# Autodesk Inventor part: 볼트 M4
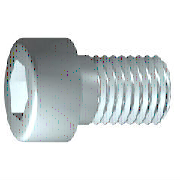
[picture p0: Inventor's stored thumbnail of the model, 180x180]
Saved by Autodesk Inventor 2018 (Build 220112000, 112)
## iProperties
IsCustomPart: 1
Created: 2012-02
Part Number: 볼트 M4
Material: 강철, 연강
Description: 6각머리 태핑 나사
Document SubType Name: Modeling
Standard: KS B 1003
Designer: mduedu
Standards Organization: KS
Language: ko-KR
Size Designation: M 4 x 12
Categories: <MemberInstance><Categories><Category DisplayName="조임쇠" InternalName="e4da775c-781d-43d5-af7c-5136215cf5a6" Mnemonic="FSTN"><Category DisplayName="볼트" InternalN
Density: 1 g/cm^3
Appearance: 강철
Author: mduedu
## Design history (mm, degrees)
sketch "스케치1"
  geometry: L1 (-1, 0)-(12, 0); L2 (12, 0)-(12, 2); L3 (12, 2)-(1.75, 2); L4 (1.75, 2)-(1.32, 2); L5 (1.32, 2)-(0, 2); L6 (0, 2)-(0, 3.5); L7 (0, 3.5)-(-4, 3.5); L8 (-4, 3.5)-(-4, 1.732); L9 (-4, 1.732)-(-2, 1.732); L10 (-2, 1.732)-(-1, 0); L11 (-7.2, 0)-(15.2, 0) reference; L12 (0, -0.7)-(0, 4.2) reference; L13 (1.75, 2)-(0, 2)
  constraints: 22 end point, 6 parallel, 2 collinear, 2 perpendicular, 1 horizontal, 1 point on line
  dimensions: "d1" = 10.25 distance from line of L3.end L2 (= GEL); "d2" = 0.42952 distance of L4.end L3.end (computed from GAL); "d3" = 4 distance between parallel lines of L8 L6 (= KOH); "d4" = 2 distance of L8.end L9.end (= INTI); "d5" = 60 deg angle of L10 L1; "d6" = 4 diameter of L3 L1 (= GD); "d7" = 4 diameter of L5 L1 (= BDM); "d8" = 3.4641 diameter of L9 L1 (= 1.1547 x SW); "d9" = 7 diameter of L7 L1 (= KOD); "d26" = 12 distance between parallel lines of L12 L2 (= NLG)
revolve "본체" sketch "스케치1" stored, may be unused: angle "d10" = 90 deg
sketch "스케치2"
  geometry: L1 (0, -4.9)-(0, 4.9) reference; L2 (-4.9, 0)-(4.9, 0) reference; L3 (1.732, 0)-(0.866, -1.5); L4 (0.866, -1.5)-(-0.866, -1.5); L5 (-0.866, -1.5)-(-1.732, 0); L6 (-1.732, 0)-(-0.866, 1.5); L7 (-0.866, 1.5)-(0.866, 1.5); L8 (0.866, 1.5)-(1.732, 0); 2 further points
  constraints: 12 end point, 1 coincident, 1 horizontal alignment, 1 point on line, 12 other
extrude "슬롯" join sketch "스케치2" stored distance "d11" = 10; taper "d12" = 0 deg
workplane "Work Plane1"
fillet "Fillet2" dims "d30" = 0.1 (= R)
body "Solid1"
fillet "모깎기1" dims "d17" = 0.4 (= RR)
feature "스레드" dims "d13" = 10.25 (= GEL), "d14" = 0
chamfer "모따기1" distance "d15" = 0.42941 (= -0.5 x SPD + 0.5 x GD); stored, may be unused: second distance "d16" = 0.42941 (= GUL), angle "d27" = 45 deg
other parameters: "GD" = 4 (= NND) [user parameter; used in 2 equation terms], "NLG" = 12 [user parameter; used in 1 equation term], "GEL" = 10.25 [user parameter; used in 2 equation terms], "KOD" = 7 [user parameter; used in 1 equation term], "KOH" = 4 [user parameter; used in 1 equation term], "INTI" = 2 [user parameter; used in 1 equation term], "GAL" = 0.42941 (= 0.61345 x PTC) [user parameter; used in 1 equation term], "GUL" = 0.42941 (= 0.61345 x PTC) [user parameter; used in 1 equation term], "BDM" = 4 (= NND) [user parameter; used in 1 equation term], "SW" = 3 [user parameter; used in 2 equation terms], "RR" = 0.4 [user parameter; used in 1 equation term], "SPD" = 3.14117 (= NND - 1.2269 x PTC) [user parameter; used in 1 equation term], "d19" = 0, "d28" = 0, "d29" = 0, "R" = 0.1 [user parameter; used in 1 equation term], "PHH" = 0.2 [user parameter], "GD1" = 3.14117 (= THREADDIA - 1.2269 x PTC) [user parameter], "THREADDIA" = 4 [user parameter; used in 1 equation term], "FAWI" = 45 deg [user parameter], "TPU" = 14.28571 (computed from PTC) [user parameter], "PTC" = 0.7 [user parameter; used in 5 equation terms], "NND" = 4 [user parameter; used in 3 equation terms], "TOA" = 30 deg [user parameter], "E0" = 3.465 (= 1.155 x SW) [user parameter]
